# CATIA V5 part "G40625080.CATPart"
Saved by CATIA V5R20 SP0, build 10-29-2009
Part number: G40625080
Revision: 6
Definition: design
Nomenclature: G40625080
Source: made
Description: NOT SPECIFIED
Bounding box of the stored display mesh (mm): x -40 to 40, y -25 to 0, z -10 to 10
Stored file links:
  C:\Users\Raffaele\Desktop\3D X SITO CF\BOLEX\30-GUIDE STRIP REF 406\G40625080.CATPart
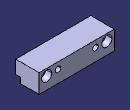
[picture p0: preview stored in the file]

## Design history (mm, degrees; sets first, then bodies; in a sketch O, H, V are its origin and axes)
Body1 "MANIFOLD_SOLID_BREP #3064" (main body)
  Solid1: solid without history
Body2 "MANIFOLD_SOLID_BREP #3202"
  Solid2: solid without history
Body3 "MANIFOLD_SOLID_BREP #3340"
  Solid3: solid without history
Body4 "MANIFOLD_SOLID_BREP #3478"
  Solid4: solid without history
Body5 "MANIFOLD_SOLID_BREP #3616"
  Solid5: solid without history
Body6 "MANIFOLD_SOLID_BREP #3754"
  Solid6: solid without history
Body7 "MANIFOLD_SOLID_BREP #3866"
  Solid7: solid without history
Body8 "MANIFOLD_SOLID_BREP #3978"
  Solid8: solid without history
Body9 "MANIFOLD_SOLID_BREP #4090"
  Solid9: solid without history
Body10 "MANIFOLD_SOLID_BREP #4202"
  Solid10: solid without history
Body11 "MANIFOLD_SOLID_BREP #4314"
  Solid11: solid without history
Body12 "MANIFOLD_SOLID_BREP #4426"
  Solid12: solid without history
Body13 "MANIFOLD_SOLID_BREP #4564"
  Solid13: solid without history
Body14 "MANIFOLD_SOLID_BREP #4702"
  Solid14: solid without history
Body15 "MANIFOLD_SOLID_BREP #4814"
  Solid15: solid without history
Body16 "MANIFOLD_SOLID_BREP #4926"
  Solid16: solid without history
Body17 "MANIFOLD_SOLID_BREP #5038"
  Solid17: solid without history
Body18 "MANIFOLD_SOLID_BREP #5150"
  Solid18: solid without history
Body19 "MANIFOLD_SOLID_BREP #5262"
  Solid19: solid without history
Body20 "MANIFOLD_SOLID_BREP #5374"
  Solid20: solid without history
Body21 "MANIFOLD_SOLID_BREP #5486"
  Solid21: solid without history
Body22 "MANIFOLD_SOLID_BREP #5598"
  Solid22: solid without history
Body23 "MANIFOLD_SOLID_BREP #5710"
  Solid23: solid without history
Body24 "MANIFOLD_SOLID_BREP #5822"
  Solid24: solid without history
